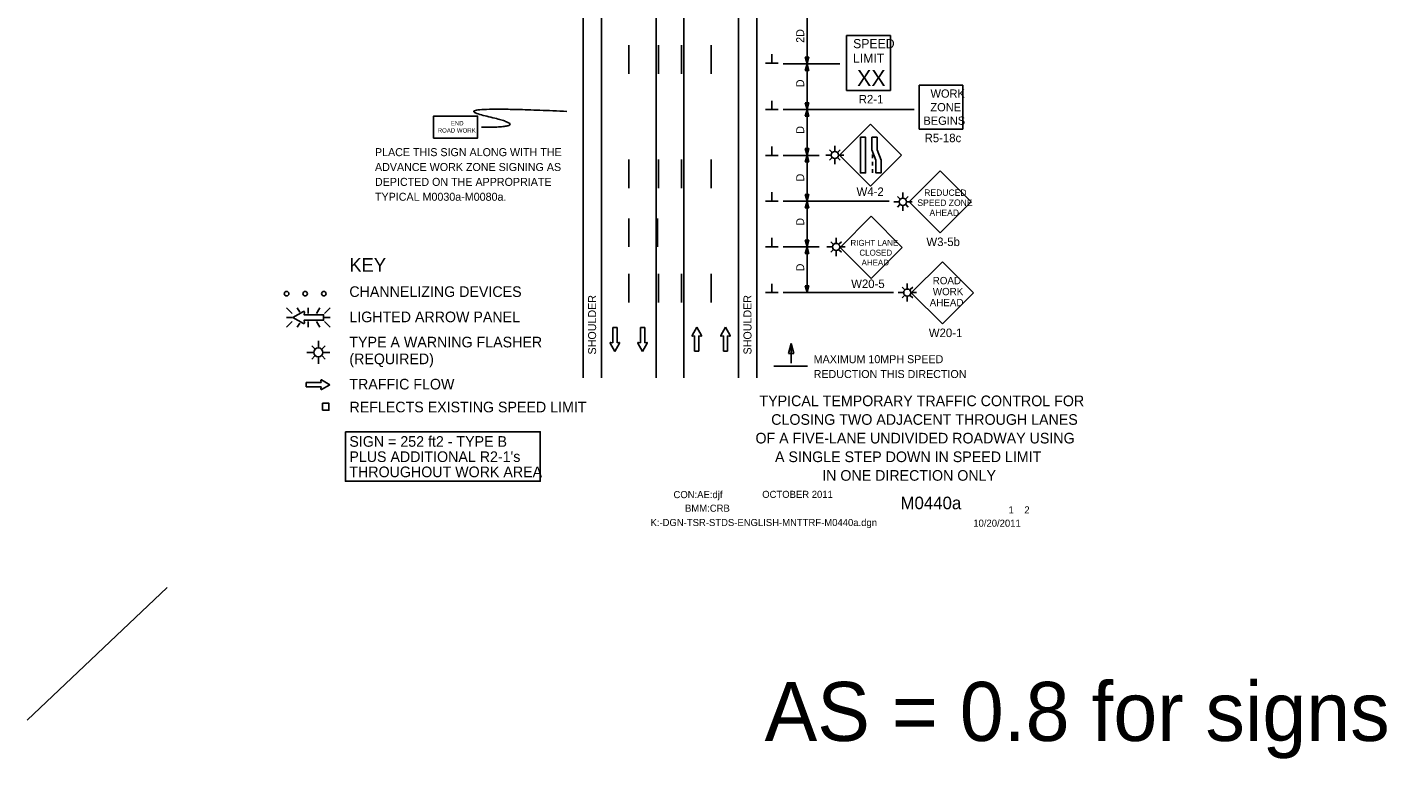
# Model space of a CAD drawing. Extents: x 16525 to 18478, y 5730 to 6927.
# Drawn here: x 16525 to 17715, y 5730 to 6370 of the extents above; entities that cross this region are included whole.
import ezdxf

# ---------------------------------------------------------------- set-up
doc = ezdxf.new("R2010")
doc.units = 0
for name, color, linetype in [('ALI_LEGAL_EX', 7, 'Continuous'), ('BORDER', 7, 'Continuous'), ('BORDER_SIGNAL_WO', 7, 'Continuous'), ('MT_SCRATCH_LEVEL_E', 7, 'Continuous'), ('PAVT_EDGE_EX', 7, 'Continuous'), ('TRAFFIC_SIGNS_PR', 7, 'Continuous'), ('TYPICAL_TEXT_DIMEN_EX', 7, 'Continuous'), ('TYPICAL_TEXT_DIMEN_PR', 7, 'Continuous')]:
    doc.layers.add(name, color=color, linetype=linetype)

msp = doc.modelspace()

# ---------------------------------------------------------------- linework, layer by layer
at = {"layer": 'ALI_LEGAL_EX'}
for points in [[(17051.6, 6354.2), (17051.6, 6329.2)], [(17077.6, 6354.2), (17077.6, 6329.2)], [(17097.6, 6354.2), (17097.6, 6329.2)], [(17123.6, 6354.2), (17123.6, 6329.2)], [(17051.6, 6254.2), (17051.6, 6229.2)], [(17077.6, 6254.2), (17077.6, 6229.2)], [(17097.6, 6254.2), (17097.6, 6229.2)], [(17123.6, 6254.2), (17123.6, 6229.2)], [(17051.6, 6154.2), (17051.6, 6129.2)], [(17077.6, 6154.2), (17077.6, 6129.2)], [(17097.6, 6154.2), (17097.6, 6129.2)], [(17123.6, 6154.2), (17123.6, 6129.2)]]:
    msp.add_lwpolyline(points, dxfattribs=at)
at = {"layer": 'MT_SCRATCH_LEVEL_E'}
for p, q in [((17041.3, 6107.2), (17037.5, 6107.2)), ((17037.5, 6107.2), (17037.5, 6093.9)), ((17041.3, 6107.2), (17037.5, 6107.2)), ((17037.5, 6107.2), (17037.5, 6093.9)), ((17041.3, 6093.9), (17041.3, 6107.2)), ((17041.3, 6093.9), (17041.3, 6107.2)), ((17065.5, 6107.2), (17061.8, 6107.2)), ((17061.8, 6107.2), (17061.8, 6093.9)), ((17065.5, 6107.2), (17061.8, 6107.2)), ((17061.8, 6107.2), (17061.8, 6093.9)), ((17065.5, 6093.9), (17065.5, 6107.2)), ((17065.5, 6093.9), (17065.5, 6107.2)), ((17111, 6107.6), (17106.9, 6100.4)), ((17111, 6107.6), (17106.9, 6100.4)), ((17115.2, 6100.4), (17111, 6107.6)), ((17115.2, 6100.4), (17111, 6107.6)), ((17136.1, 6107.6), (17132, 6100.4)), ((17136.1, 6107.6), (17132, 6100.4)), ((17140.3, 6100.4), (17136.1, 6107.6)), ((17140.3, 6100.4), (17136.1, 6107.6)), ((17035.3, 6093.5), (17039.4, 6086.3)), ((17035.3, 6093.5), (17039.4, 6086.3)), ((17037.5, 6093.9), (17035.7, 6094.2)), ((17037.5, 6093.9), (17035.7, 6094.2)), ((17039.4, 6086.3), (17043.5, 6093.5)), ((17039.4, 6086.3), (17043.5, 6093.5)), ((17043, 6094.2), (17041.3, 6093.9)), ((17043, 6094.2), (17041.3, 6093.9)), ((17059.5, 6093.5), (17063.7, 6086.3)), ((17059.5, 6093.5), (17063.7, 6086.3)), ((17061.8, 6093.9), (17060, 6094.2)), ((17061.8, 6093.9), (17060, 6094.2)), ((17063.7, 6086.3), (17067.8, 6093.5)), ((17063.7, 6086.3), (17067.8, 6093.5)), ((17067.3, 6094.2), (17065.5, 6093.9)), ((17067.3, 6094.2), (17065.5, 6093.9)), ((17107.4, 6099.7), (17109.2, 6100)), ((17107.4, 6099.7), (17109.2, 6100)), ((17109.2, 6100), (17109.2, 6086.7)), ((17109.2, 6100), (17109.2, 6086.7)), ((17112.9, 6086.7), (17112.9, 6100)), ((17112.9, 6100), (17114.7, 6099.7)), ((17112.9, 6086.7), (17112.9, 6100)), ((17112.9, 6100), (17114.7, 6099.7)), ((17132.5, 6099.7), (17134.3, 6100)), ((17132.5, 6099.7), (17134.3, 6100)), ((17134.3, 6100), (17134.3, 6086.7)), ((17134.3, 6100), (17134.3, 6086.7)), ((17138, 6086.7), (17138, 6100)), ((17138, 6100), (17139.8, 6099.7)), ((17138, 6086.7), (17138, 6100)), ((17138, 6100), (17139.8, 6099.7)), ((17109.2, 6086.7), (17112.9, 6086.7)), ((17109.2, 6086.7), (17112.9, 6086.7)), ((17134.3, 6086.7), (17138, 6086.7)), ((17134.3, 6086.7), (17138, 6086.7)), ((16782.6, 6059.1), (16769.3, 6059.1)), ((16769.3, 6059.1), (16769.3, 6055.4)), ((16782.6, 6059.1), (16769.3, 6059.1)), ((16769.3, 6059.1), (16769.3, 6055.4)), ((16769.3, 6055.4), (16782.6, 6055.4)), ((16769.3, 6055.4), (16782.6, 6055.4)), ((16782.3, 6060.9), (16782.6, 6059.1)), ((16782.3, 6060.9), (16782.6, 6059.1)), ((16782.6, 6055.4), (16782.3, 6053.6)), ((16782.6, 6055.4), (16782.3, 6053.6)), ((16790.2, 6057.3), (16782.9, 6061.4)), ((16790.2, 6057.3), (16782.9, 6061.4)), ((16782.9, 6053.1), (16790.2, 6057.3)), ((16782.9, 6053.1), (16790.2, 6057.3))]:
    msp.add_line(p, q, dxfattribs=at)
for centre, start, end in [((17107.3, 6100.1), 150.4248, 279.9638), ((17107.3, 6100.1), 150.4248, 279.9638), ((17114.8, 6100.1), 260.0362, 29.7731), ((17114.8, 6100.1), 260.0362, 29.7731), ((17132.4, 6100.1), 150.4248, 279.9638), ((17132.4, 6100.1), 150.4248, 279.9638), ((17139.9, 6100.1), 260.0362, 29.7731), ((17139.9, 6100.1), 260.0362, 29.7731), ((17035.7, 6093.8), 80.0362, 209.7731), ((17035.7, 6093.8), 80.0362, 209.7731), ((17043.1, 6093.8), 330.4248, 99.9638), ((17043.1, 6093.8), 330.4248, 99.9638), ((17059.9, 6093.8), 80.0362, 209.7731), ((17059.9, 6093.8), 80.0362, 209.7731), ((17067.4, 6093.8), 330.4248, 99.9638), ((17067.4, 6093.8), 330.4248, 99.9638), ((16782.7, 6061), 60.4248, 189.9638), ((16782.7, 6061), 60.4248, 189.9638), ((16782.7, 6053.5), 170.0362, 299.7731), ((16782.7, 6053.5), 170.0362, 299.7731)]:
    msp.add_arc(centre, 0.463, start, end, dxfattribs=at)
at = {"layer": 'PAVT_EDGE_EX'}
for p, q in [((17011.6, 6917.6), (17011.6, 6063.2)), ((17027.6, 6917.6), (17027.6, 6063.2)), ((17075.6, 6917.6), (17075.6, 6063.2)), ((17147.6, 6917.6), (17147.6, 6063.2)), ((17163.6, 6917.6), (17163.6, 6063.2)), ((17099.6, 6464.3), (17099.6, 6063.2))]:
    msp.add_line(p, q, dxfattribs=at)
for points in [[(17051.6, 6177.7), (17051.6, 6202.7)], [(17076.6, 6177.7), (17076.6, 6202.7)]]:
    msp.add_lwpolyline(points, dxfattribs=at)
at = {"layer": 'TRAFFIC_SIGNS_PR'}
for p, q in [((17242.1, 6362.6), (17280.5, 6362.6)), ((17242.1, 6314.6), (17242.1, 6362.6)), ((17280.5, 6314.6), (17280.5, 6362.6)), ((17242.1, 6314.6), (17280.5, 6314.6)), ((17305.5, 6280.8), (17305.5, 6319.2)), ((17305.5, 6319.2), (17343.9, 6319.2)), ((17343.9, 6280.8), (17343.9, 6319.2)), ((17263.1, 6285.1), (17235.9, 6258)), ((17290.2, 6258), (17263.1, 6285.1)), ((17305.5, 6280.8), (17343.9, 6280.8)), ((17228.6, 6258.1), (17223.8, 6258.1)), ((17229.3, 6260.6), (17227.2, 6262.7)), ((17229.3, 6255.6), (17227.2, 6253.5)), ((17231.8, 6261.7), (17231.8, 6266.2)), ((17234.3, 6260.6), (17236.4, 6262.7)), ((17234.3, 6255.6), (17236.4, 6253.5)), ((17234.9, 6258.1), (17239.8, 6258.1)), ((17235.9, 6258), (17263.1, 6230.8)), ((17263.1, 6230.8), (17290.2, 6258)), ((17264.7, 6258.5), (17264.7, 6255.3)), ((17231.8, 6250.1), (17231.8, 6254.5)), ((17264.7, 6252.1), (17264.7, 6248.9)), ((17264.7, 6245.7), (17264.7, 6242.5)), ((17324, 6244.3), (17296.8, 6217.1)), ((17351.1, 6217.1), (17324, 6244.3)), ((17288.7, 6219.7), (17286.6, 6221.8)), ((17291.3, 6220.8), (17291.3, 6225.3)), ((17293.8, 6219.7), (17295.9, 6221.8)), ((17288.1, 6217.2), (17283.3, 6217.2)), ((17288.7, 6214.7), (17286.6, 6212.6)), ((17291.3, 6209.2), (17291.3, 6213.6)), ((17293.8, 6214.7), (17295.9, 6212.6)), ((17294.4, 6217.2), (17299.3, 6217.2)), ((17296.8, 6217.1), (17324, 6190)), ((17324, 6190), (17351.1, 6217.1)), ((17263.6, 6204.5), (17236.4, 6177.3)), ((17290.7, 6177.3), (17263.6, 6204.5)), ((17232.9, 6181.2), (17232.9, 6185.7)), ((17229.8, 6177.7), (17224.9, 6177.7)), ((17230.4, 6180.2), (17228.3, 6182.3)), ((17230.4, 6175.2), (17228.3, 6173.1)), ((17232.9, 6169.7), (17232.9, 6174.1)), ((17235.4, 6180.2), (17237.5, 6182.3)), ((17235.4, 6175.2), (17237.5, 6173.1)), ((17236.1, 6177.7), (17240.9, 6177.7)), ((17236.4, 6177.3), (17263.6, 6150.2)), ((17263.6, 6150.2), (17290.7, 6177.3)), ((17325.9, 6164.8), (17298.7, 6137.6)), ((17353.1, 6137.6), (17325.9, 6164.8)), ((17292.1, 6137.8), (17287.2, 6137.8)), ((17292.7, 6140.4), (17290.6, 6142.5)), ((17295.2, 6141.4), (17295.2, 6145.9)), ((17297.8, 6140.4), (17299.9, 6142.5)), ((17298.4, 6137.8), (17303.3, 6137.8)), ((17298.7, 6137.6), (17325.9, 6110.4)), ((17325.9, 6110.4), (17353.1, 6137.6)), ((16752.1, 6124.6), (16757.1, 6119.6)), ((16763.9, 6120.7), (16761.7, 6124.6)), ((16771.2, 6119.6), (16771.2, 6124.6)), ((16778.5, 6119.6), (16781.3, 6124.6)), ((16785.4, 6119.6), (16790.3, 6124.6)), ((17292.7, 6135.3), (17290.6, 6133.2)), ((17295.2, 6129.9), (17295.2, 6134.3)), ((17297.8, 6135.3), (17299.9, 6133.2)), ((16757.1, 6116.1), (16752.1, 6116.1)), ((16752.1, 6107.6), (16757.1, 6112.5)), ((16771.2, 6112.5), (16771.2, 6107.6)), ((16781.4, 6107.6), (16778.5, 6112.5)), ((16785.4, 6116.1), (16790.3, 6116.1)), ((16785.4, 6112.5), (16790.3, 6107.6)), ((16761.7, 6107.6), (16763.8, 6111.2)), ((16777, 6088.6), (16774.4, 6091.3)), ((16780.1, 6089.9), (16780.1, 6095.6)), ((16783.3, 6088.6), (16785.9, 6091.3)), ((16776.2, 6085.5), (16770.1, 6085.5)), ((16777, 6082.4), (16774.4, 6079.7)), ((16780.1, 6075.5), (16780.1, 6081.1)), ((16783.3, 6082.4), (16785.9, 6079.7)), ((16784.1, 6085.5), (16790.2, 6085.5))]:
    msp.add_line(p, q, dxfattribs=at)
for points in [[(16880.9, 6272.9), (16919.3, 6272.9), (16919.3, 6292.1), (16880.9, 6292.1)], [(17254.2, 6273.7), (17254.2, 6242.5), (17258.7, 6242.5), (17258.7, 6273.7)], [(17264.3, 6273.7), (17264.3, 6262.5), (17267.7, 6253.6), (17267.7, 6242.5), (17272.2, 6242.5), (17272.2, 6253.6), (17268.8, 6262.5), (17268.8, 6273.7)], [(16783.8, 6034.9), (16789.3, 6034.9), (16789.3, 6041.1), (16783.8, 6041.1)]]:
    msp.add_lwpolyline(points, close=True, dxfattribs=at)
for points in [[(16767.2, 6121.3), (16757.9, 6116.1), (16767.2, 6110.7)], [(16768, 6111.4), (16767.6, 6113.6), (16784.6, 6113.6), (16784.6, 6118.4), (16767.6, 6118.4), (16768, 6120.7)]]:
    msp.add_lwpolyline(points, dxfattribs=at)
for centre, radius in [((17231.8, 6258.1), 3.15), ((17291.3, 6217.2), 3.15), ((17232.9, 6177.7), 3.15), ((16752.3, 6136.9), 2), ((16768.6, 6136.9), 2), ((16784.9, 6136.9), 2), ((17295.2, 6137.8), 3.15), ((16780.1, 6085.5), 3.94)]:
    msp.add_circle(centre, radius, dxfattribs=at)
for centre, radius, start, end in [((16767.4, 6120.8), 0.598, 350.7308, 118.8916), ((16767.4, 6111.3), 0.597, 241.4833, 9.9593)]:
    msp.add_arc(centre, radius, start, end, dxfattribs=at)
msp.add_open_spline([(16922.9, 6282.3), (16970.1, 6282.3), (16885.1, 6301.6), (16997.4, 6296.2)], degree=2, dxfattribs=at)
at = {"layer": 'TYPICAL_TEXT_DIMEN_EX'}
msp.add_lwpolyline([(16803.8, 6016.1), (16974.2, 6016.1), (16974.2, 5972.8), (16803.8, 5972.8)], close=True, dxfattribs=at)
at = {"layer": 'TYPICAL_TEXT_DIMEN_PR'}
for p, q in [((17207.6, 6377.8), (17207.6, 6337.8)), ((17182.3, 6338.5), (17171.1, 6338.5)), ((17176.7, 6338.5), (17176.7, 6346.3)), ((17207.6, 6337.8), (17206, 6343.7)), ((17206, 6343.7), (17207.6, 6343.7)), ((17207.6, 6343.7), (17209.2, 6343.7)), ((17209.2, 6343.7), (17207.6, 6337.8)), ((17186.6, 6337.8), (17236.2, 6337.8)), ((17206, 6332), (17207.6, 6337.8)), ((17207.6, 6332), (17206, 6332)), ((17207.6, 6337.8), (17207.6, 6297.8)), ((17207.6, 6337.8), (17209.2, 6332)), ((17209.2, 6332), (17207.6, 6332)), ((17176.7, 6297.8), (17176.7, 6305.6)), ((17207.6, 6297.8), (17206, 6303.7)), ((17206, 6303.7), (17207.6, 6303.7)), ((17207.6, 6303.7), (17209.2, 6303.7)), ((17209.2, 6303.7), (17207.6, 6297.8)), ((17182.3, 6297.8), (17171.1, 6297.8)), ((17186.6, 6297.8), (17301.3, 6297.8)), ((17206, 6292), (17207.6, 6297.8)), ((17207.6, 6292), (17206, 6292)), ((17207.6, 6297.8), (17207.6, 6257.8)), ((17207.6, 6297.8), (17209.2, 6292)), ((17209.2, 6292), (17207.6, 6292)), ((17182.3, 6257.8), (17171.1, 6257.8)), ((17176.7, 6257.8), (17176.7, 6265.6)), ((17186.6, 6257.8), (17218.2, 6257.8)), ((17207.6, 6257.8), (17206, 6263.7)), ((17206, 6263.7), (17207.6, 6263.7)), ((17206, 6252), (17207.6, 6257.8)), ((17207.6, 6263.7), (17209.2, 6263.7)), ((17209.2, 6263.7), (17207.6, 6257.8)), ((17207.6, 6257.8), (17207.6, 6217.8)), ((17207.6, 6257.8), (17209.2, 6252)), ((17207.6, 6252), (17206, 6252)), ((17209.2, 6252), (17207.6, 6252)), ((17176.7, 6217.8), (17176.7, 6225.6)), ((17207.6, 6217.8), (17206, 6223.7)), ((17206, 6223.7), (17207.6, 6223.7)), ((17207.6, 6223.7), (17209.2, 6223.7)), ((17209.2, 6223.7), (17207.6, 6217.8)), ((17182.3, 6217.8), (17171.1, 6217.8)), ((17186.6, 6217.8), (17279.3, 6217.8)), ((17206, 6212), (17207.6, 6217.8)), ((17207.6, 6212), (17206, 6212)), ((17207.6, 6217.8), (17207.6, 6177.8)), ((17207.6, 6217.8), (17209.2, 6212)), ((17209.2, 6212), (17207.6, 6212)), ((17176.7, 6177.8), (17176.7, 6185.6)), ((17207.6, 6177.8), (17206, 6183.7)), ((17206, 6183.7), (17207.6, 6183.7)), ((17207.6, 6183.7), (17209.2, 6183.7)), ((17209.2, 6183.7), (17207.6, 6177.8)), ((17182.3, 6177.8), (17171.1, 6177.8)), ((17186.6, 6177.8), (17218.2, 6177.8)), ((17206, 6172), (17207.6, 6177.8)), ((17207.6, 6172), (17206, 6172)), ((17207.6, 6177.8), (17207.6, 6137.8)), ((17207.6, 6177.8), (17209.2, 6172)), ((17209.2, 6172), (17207.6, 6172)), ((17182.3, 6137.8), (17171.1, 6137.8)), ((17176.7, 6137.8), (17176.7, 6145.6)), ((17186.6, 6137.8), (17283.1, 6137.8)), ((17207.6, 6137.8), (17206, 6143.7)), ((17206, 6143.7), (17207.6, 6143.7)), ((17207.6, 6143.7), (17209.2, 6143.7)), ((17209.2, 6143.7), (17207.6, 6137.8)), ((17191.3, 6084.5), (17193.6, 6093.3)), ((17193.6, 6076.1), (17193.6, 6093.3)), ((17193.6, 6093.3), (17196, 6084.5)), ((17193.6, 6084.5), (17191.3, 6084.5)), ((17196, 6084.5), (17193.6, 6084.5)), ((17207.8, 6073.6), (17178.4, 6073.6)), ((16647.8, 5880), (16525.4, 5763.9))]:
    msp.add_line(p, q, dxfattribs=at)

# ---------------------------------------------------------------- texts
at = {"layer": 'BORDER'}
for s, p in [('TYPICAL TEMPORARY TRAFFIC CONTROL FOR', (17165.9, 6038.5)), ('CLOSING TWO ADJACENT THROUGH LANES', (17176.2, 6022.2)), ('OF A FIVE-LANE UNDIVIDED ROADWAY USING', (17162.4, 6005.9)), ('A SINGLE STEP DOWN IN SPEED LIMIT', (17179.5, 5989.6)), (' IN ONE DIRECTION ONLY', (17217.3, 5973.3))]:
    msp.add_text(s, height=9.3, dxfattribs=at).set_placement(p)
at = {"layer": 'BORDER_SIGNAL_WO'}
for s, height, p in [('CON:AE:djf', 6.2, (17090.7, 5958.1)), ('    OCTOBER 2011    ', 6.2, (17159.1, 5958.3)), ('    M0440a   ', 11, (17272.9, 5948.4)), ('BMM:CRB   ', 6.2, (17100.8, 5946.2)), (' 1    2 ', 6.2, (17381.4, 5944.7)), ('K:-DGN-TSR-STDS-ENGLISH-MNTTRF-M0440a.dgn         ', 6.2, (17070.6, 5933.7)), ('10/20/2011    ', 6.2, (17352.9, 5933.1)), ('AS = 0.8 for signs', 51.61, (17170.4, 5745.8))]:
    msp.add_text(s, height=height, dxfattribs=at).set_placement(p)
at = {"layer": 'TRAFFIC_SIGNS_PR'}
for s, height, p in [('SPEED', 8, (17247.8, 6351.5)), ('LIMIT', 8, (17247.7, 6338.7)), ('XX', 14.03, (17251.2, 6318.4)), ('WORK', 7.22, (17315.5, 6308.2)), ('R2-1', 7.44, (17252.7, 6303.2)), ('ZONE', 7.22, (17315.4, 6296.3)), ('BEGINS', 7.22, (17309.3, 6284.5)), ('ROAD WORK', 3.83, (16884.5, 6277.7)), ('END', 3.83, (16895.9, 6284)), ('R5-18c', 7.44, (17310.3, 6269.3)), ('PLACE THIS SIGN ALONG WITH THE', 7, (16829.6, 6257.1)), ('ADVANCE WORK ZONE SIGNING AS', 7, (16829.6, 6244.1)), ('DEPICTED ON THE APPROPRIATE', 7, (16829.6, 6231.1)), ('TYPICAL M0030a-M0080a.', 7, (16829.6, 6218.1)), ('W4-2', 7.44, (17250.8, 6222.3)), ('SPEED ZONE', 5.6, (17304, 6213.6)), ('REDUCED', 5.6, (17310, 6222.4)), ('AHEAD', 5.6, (17314.6, 6204.8)), ('RIGHT LANE', 5.2, (17245.5, 6178.7)), ('W3-5b', 7.44, (17311.9, 6178.5)), ('CLOSED', 5.2, (17253.3, 6170.1)), ('AHEAD', 5.2, (17255.2, 6161.5)), ('W20-5', 7.44, (17246.1, 6141.8)), ('ROAD', 6.41, (17317.4, 6145.1)), ('WORK', 6.41, (17317.5, 6135.5)), ('AHEAD', 6.41, (17314.8, 6125.9)), ('W20-1', 7.45, (17314, 6098.9))]:
    msp.add_text(s, height=height, dxfattribs=at).set_placement(p)
at = {"layer": 'TYPICAL_TEXT_DIMEN_EX'}
for s, height, p in [('KEY', 12, (16807.2, 6156)), ('CHANNELIZING DEVICES', 9.3, (16807.2, 6134)), ('LIGHTED ARROW PANEL', 9.3, (16807.2, 6111.9)), ('TYPE A WARNING FLASHER', 9.3, (16807.2, 6089.9)), ('(REQUIRED)', 9.3, (16807.2, 6075.2)), ('TRAFFIC FLOW', 9.3, (16807.2, 6053.1)), ('REFLECTS EXISTING SPEED LIMIT', 9.3, (16807.3, 6033.1)), ('SIGN = 252 ft2 - TYPE B', 9.3, (16807.2, 6003)), ("PLUS ADDITIONAL R2-1's", 9.3, (16807.2, 5989.7)), ('THROUGHOUT WORK AREA', 9.3, (16807.2, 5976.4))]:
    msp.add_text(s, height=height, dxfattribs=at).set_placement(p)
at = {"layer": 'TYPICAL_TEXT_DIMEN_PR'}
for s, p in [('2D', (17205, 6356.2)), ('D', (17205, 6317.4)), ('D', (17205, 6276.7)), ('D', (17205, 6235)), ('D', (17205, 6196.3)), ('D', (17205, 6156.4)), ('SHOULDER', (17023, 6083.7)), ('SHOULDER', (17158.9, 6083.7))]:
    msp.add_text(s, height=7, rotation=90, dxfattribs=at).set_placement(p)
for s, p in [('MAXIMUM 10MPH SPEED', (17213.3, 6076.1)), ('REDUCTION THIS DIRECTION', (17213.3, 6063.1))]:
    msp.add_text(s, height=7, dxfattribs=at).set_placement(p)

doc.saveas('drawing.dxf')
